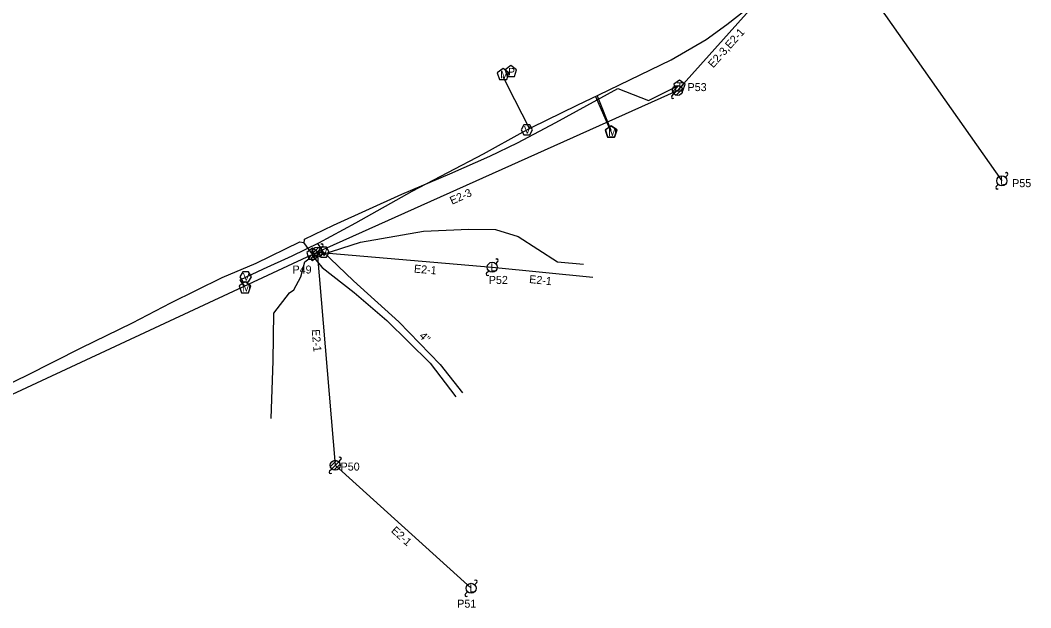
# Model space of a CAD drawing. Extents: x 1741604 to 1825760, y 1164229 to 1194908.
# Drawn here: x 1756853 to 1757358, y 1169162 to 1169455 of the extents above; entities that cross this region are included whole.
import ezdxf

# ---------------------------------------------------------------- set-up
doc = ezdxf.new("R2010")
doc.units = 0
for name, color, linetype in [('RD_EX_SU_H2O', 7, 'Continuous'), ('RD_EX_SU_Ovhd', 7, 'Continuous'), ('RD_EX_SU_Pole', 7, 'Continuous'), ('RD_EX_SU_Telecom', 7, 'Continuous'), ('RD_EX_SU_TX_H2O', 7, 'Continuous'), ('RD_EX_SU_TX_Pole', 7, 'Continuous')]:
    doc.layers.add(name, color=color, linetype=linetype)

# ---------------------------------------------------------------- blocks, each defined once
blk = doc.blocks.new('SUE_WM')
at = {"layer": 'RD_EX_SU_H2O'}
blk.add_lwpolyline([(0, 3.05), (-2.9, 0.94), (-1.79, -2.47), (1.79, -2.47), (2.9, 0.94)], close=True, dxfattribs=at)
blk.add_text('M', height=3.75, dxfattribs=at).set_placement((-1.43, -1.88))
blk = doc.blocks.new('SUE_WV')
at = {"layer": 'RD_EX_SU_H2O'}
blk.add_lwpolyline([(2.89, 0), (1.44, 2.5), (-1.44, 2.5), (-2.89, 0), (-1.44, -2.5), (1.44, -2.5)], close=True, dxfattribs=at)
blk.add_text('V', height=3.75, dxfattribs=at).set_placement((-1.43, -1.88))
blk = doc.blocks.new('SUE_TPP')
at = {"layer": 'RD_EX_SU_Telecom'}
blk.add_lwpolyline([(0, 3), (-2.85, 0.93), (-1.76, -2.43), (1.76, -2.43), (2.85, 0.93)], close=True, dxfattribs=at)
blk.add_text('T', height=3.75, dxfattribs=at).set_placement((-1.25, -1.88))

msp = doc.modelspace()

# ---------------------------------------------------------------- linework, layer by layer
at = {"layer": 'RD_EX_SU_H2O'}
for p, q in [((1757141.49, 1169417.71), (1757148.47, 1169400.5)), ((1757140.67, 1169417.32), (1757148.29, 1169400.22))]:
    msp.add_line(p, q, dxfattribs=at)
for points in [[(1756965.33, 1169322.24), (1756963.21, 1169325.73), (1756974.8, 1169331.25), (1756989.08, 1169337.78), (1757002.37, 1169344.21), (1757021, 1169354.2), (1757049.09, 1169370.07), (1757084.79, 1169388.71), (1757104.65, 1169399.79), (1757108.73, 1169401.93), (1757131.58, 1169412.99), (1757142.37, 1169418.13), (1757178.58, 1169435.66), (1757196, 1169445.83), (1757206.34, 1169453.3), (1757217.04, 1169461.72), (1757228.65, 1169477.7)], [(1757107.82, 1169401.45), (1757100.47, 1169415.66), (1757094.52, 1169427.24)], [(1757001.74, 1169343.86), (1757004.27, 1169340.03), (1757019.77, 1169325.31), (1757042.39, 1169304.84), (1757063.14, 1169283.41), (1757074.27, 1169269.39)]]:
    msp.add_lwpolyline(points, dxfattribs=at)
msp.add_lwpolyline([(1757098.42, 1169432.8), (1757095.52, 1169430.69), (1757096.63, 1169427.28), (1757100.21, 1169427.28), (1757101.32, 1169430.69)], close=True, dxfattribs=at)
at = {"layer": 'RD_EX_SU_Ovhd'}
for p, q in [((1757181.7, 1169420.4), (1757254.71, 1169502.01)), ((1757254.71, 1169502.01), (1757343.85, 1169375.24)), ((1757001.63, 1169339.59), (1757181.7, 1169420.4)), ((1756708.15, 1169203.09), (1757001.63, 1169339.59)), ((1757001.63, 1169339.59), (1757010.67, 1169233.11)), ((1757001.63, 1169339.59), (1757089.13, 1169332.08)), ((1757089.13, 1169332.08), (1757139.42, 1169327.03)), ((1757010.67, 1169233.11), (1757078.55, 1169171.67))]:
    msp.add_line(p, q, dxfattribs=at)
at = {"layer": 'RD_EX_SU_Pole'}
for p, q in [((1757179.29, 1169419.76), (1757182.36, 1169422.82)), ((1757183.48, 1169422.17), (1757184.54, 1169423.23)), ((1757178.88, 1169417.58), (1757179.94, 1169418.64)), ((1757179.94, 1169418.64), (1757183.48, 1169422.17)), ((1757181.06, 1169417.99), (1757184.12, 1169421.05)), ((1757345.61, 1169377.01), (1757346.67, 1169378.07)), ((1757341.02, 1169372.42), (1757342.08, 1169373.48)), ((1756999.22, 1169338.94), (1757002.28, 1169342)), ((1757003.4, 1169341.35), (1757004.46, 1169342.41)), ((1756998.8, 1169336.76), (1756999.87, 1169337.82)), ((1756999.87, 1169337.82), (1757003.4, 1169341.35)), ((1757000.99, 1169337.17), (1757004.05, 1169340.23)), ((1757090.89, 1169333.85), (1757091.95, 1169334.91)), ((1757086.3, 1169329.25), (1757087.36, 1169330.31)), ((1757012.43, 1169234.87), (1757013.49, 1169235.94)), ((1757007.84, 1169230.28), (1757008.9, 1169231.34)), ((1757008.25, 1169232.46), (1757011.31, 1169235.52)), ((1757008.9, 1169231.34), (1757012.43, 1169234.87)), ((1757010.02, 1169230.69), (1757013.08, 1169233.75)), ((1757080.32, 1169173.44), (1757081.38, 1169174.5)), ((1757075.72, 1169168.84), (1757076.78, 1169169.9))]:
    msp.add_line(p, q, dxfattribs=at)
for centre in [(1757181.71, 1169420.4), (1757343.85, 1169375.24), (1757001.63, 1169339.59), (1757089.13, 1169332.08), (1757010.67, 1169233.11), (1757078.55, 1169171.67)]:
    msp.add_circle(centre, 2.5, dxfattribs=at)
for centre, start, end in [((1757184.01, 1169423.76), 315, 135), ((1757179.41, 1169417.05), 135, 315), ((1757346.14, 1169378.6), 315, 135), ((1757341.55, 1169371.89), 135, 315), ((1757003.93, 1169342.95), 315, 135), ((1756999.33, 1169336.23), 135, 315), ((1757091.42, 1169335.44), 315, 135), ((1757086.83, 1169328.72), 135, 315), ((1757012.96, 1169236.47), 315, 135), ((1757008.37, 1169229.75), 135, 315), ((1757080.85, 1169175.03), 315, 135), ((1757076.25, 1169168.31), 135, 315)]:
    msp.add_arc(centre, 0.75, start, end, dxfattribs=at)
at = {"layer": 'RD_EX_SU_Telecom'}
for points in [[(1756995.17, 1169343.88), (1756995.27, 1169346.03), (1757009.75, 1169353.03), (1757043.89, 1169368.52), (1757068, 1169378.78), (1757087.87, 1169387.6), (1757101.69, 1169394.24), (1757120.91, 1169404.43), (1757151.98, 1169421.3), (1757167.24, 1169415.35), (1757181.92, 1169422.71)], [(1756999.66, 1169337.88), (1757004.2, 1169338.44), (1757023.23, 1169344.64), (1757054.7, 1169350.16), (1757077.42, 1169351.12), (1757090.71, 1169350.92), (1757102.01, 1169347.48), (1757121.7, 1169334.78), (1757134.68, 1169333.63)], [(1756706.93, 1169203.78), (1756705.63, 1169208.7), (1756739.31, 1169225.47), (1756751.07, 1169231.4), (1756775.8, 1169242.36), (1756801.58, 1169252.27), (1756827.44, 1169264.14), (1756856.35, 1169277.94), (1756883.6, 1169291.76), (1756909.38, 1169304.26), (1756928.56, 1169314.26), (1756954.07, 1169326.93), (1756971.08, 1169334.18), (1756992.88, 1169344.76), (1756994.71, 1169344.5), (1756998.78, 1169338.96)], [(1756978.66, 1169256.46), (1756979.64, 1169285.32), (1756979.91, 1169309.12), (1756987.8, 1169319.34), (1756989.93, 1169320.81), (1756993.47, 1169327.28), (1756995.47, 1169334.76), (1756997.44, 1169336.29), (1756998.65, 1169338.15)], [(1756999.02, 1169338.03), (1757004.1, 1169331.95), (1757020.11, 1169319.4), (1757036.37, 1169305.42), (1757058.04, 1169284.15), (1757070.99, 1169267.33)]]:
    msp.add_lwpolyline(points, dxfattribs=at)

# ---------------------------------------------------------------- block references
at = {"layer": 'RD_EX_SU_H2O'}
for name, p in [('SUE_WM', (1757094.55, 1169428.32)), ('SUE_WV', (1757106.42, 1169400.75)), ('SUE_WM', (1757148.51, 1169399.56)), ('SUE_WM', (1757148.59, 1169399.72)), ('SUE_WV', (1757004.81, 1169339.53)), ('SUE_WV', (1756965.93, 1169327.31)), ('SUE_WM', (1756965.55, 1169321.81))]:
    msp.add_blockref(name, p, dxfattribs=at)
at = {"layer": 'RD_EX_SU_Telecom'}
for p in [(1757182.66, 1169422.55), (1756999.25, 1169338.55)]:
    msp.add_blockref('SUE_TPP', p, dxfattribs=at)

# ---------------------------------------------------------------- texts
at = {"layer": 'RD_EX_SU_H2O'}
msp.add_text('P', height=3.75, dxfattribs=at).set_placement((1757097.17, 1169427.87))
at = {"layer": 'RD_EX_SU_Ovhd'}
for s, rotation, p in [('E2-3,E2-1', 48.1817, (1757199.55, 1169431.36)), ('E2-3', 24.1717, (1757069.01, 1169363.25)), ('E2-1', 355.0957, (1757049.88, 1169329.42)), ('E2-1', 354.2657, (1757107.45, 1169324.21)), ('E2-1', 274.8493, (1756998.89, 1169300.89)), ('E2-1', 317.8531, (1757038.25, 1169200.05))]:
    msp.add_text(s, height=4, rotation=rotation, dxfattribs=at).set_placement(p)
at = {"layer": 'RD_EX_SU_Pole'}
for p in [(1757342.98, 1169373.24), (1757088.26, 1169330.08), (1757077.69, 1169169.67)]:
    msp.add_text('L', height=4, dxfattribs=at).set_placement(p)
at = {"layer": 'RD_EX_SU_TX_H2O'}
msp.add_text('4"', height=4, rotation=314.0833, dxfattribs=at).set_placement((1757052.33, 1169297.45))
at = {"layer": 'RD_EX_SU_TX_Pole'}
for s, p in [('P53', (1757186.76, 1169420.06)), ('P55', (1757349.02, 1169372.08)), ('P49', (1756989.3, 1169328.92)), ('P52', (1757087.42, 1169323.73)), ('P50', (1757013.34, 1169230.48)), ('P51', (1757071.64, 1169162))]:
    msp.add_text(s, height=4, dxfattribs=at).set_placement(p)

doc.saveas('drawing.dxf')
